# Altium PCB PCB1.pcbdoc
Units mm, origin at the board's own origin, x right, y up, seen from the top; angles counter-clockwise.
Board outline 82.72 x 77.76 mm, 2 copper layers (Top Layer, Bottom Layer); 33 components, 33 nets, 157 pads, 106 vias.
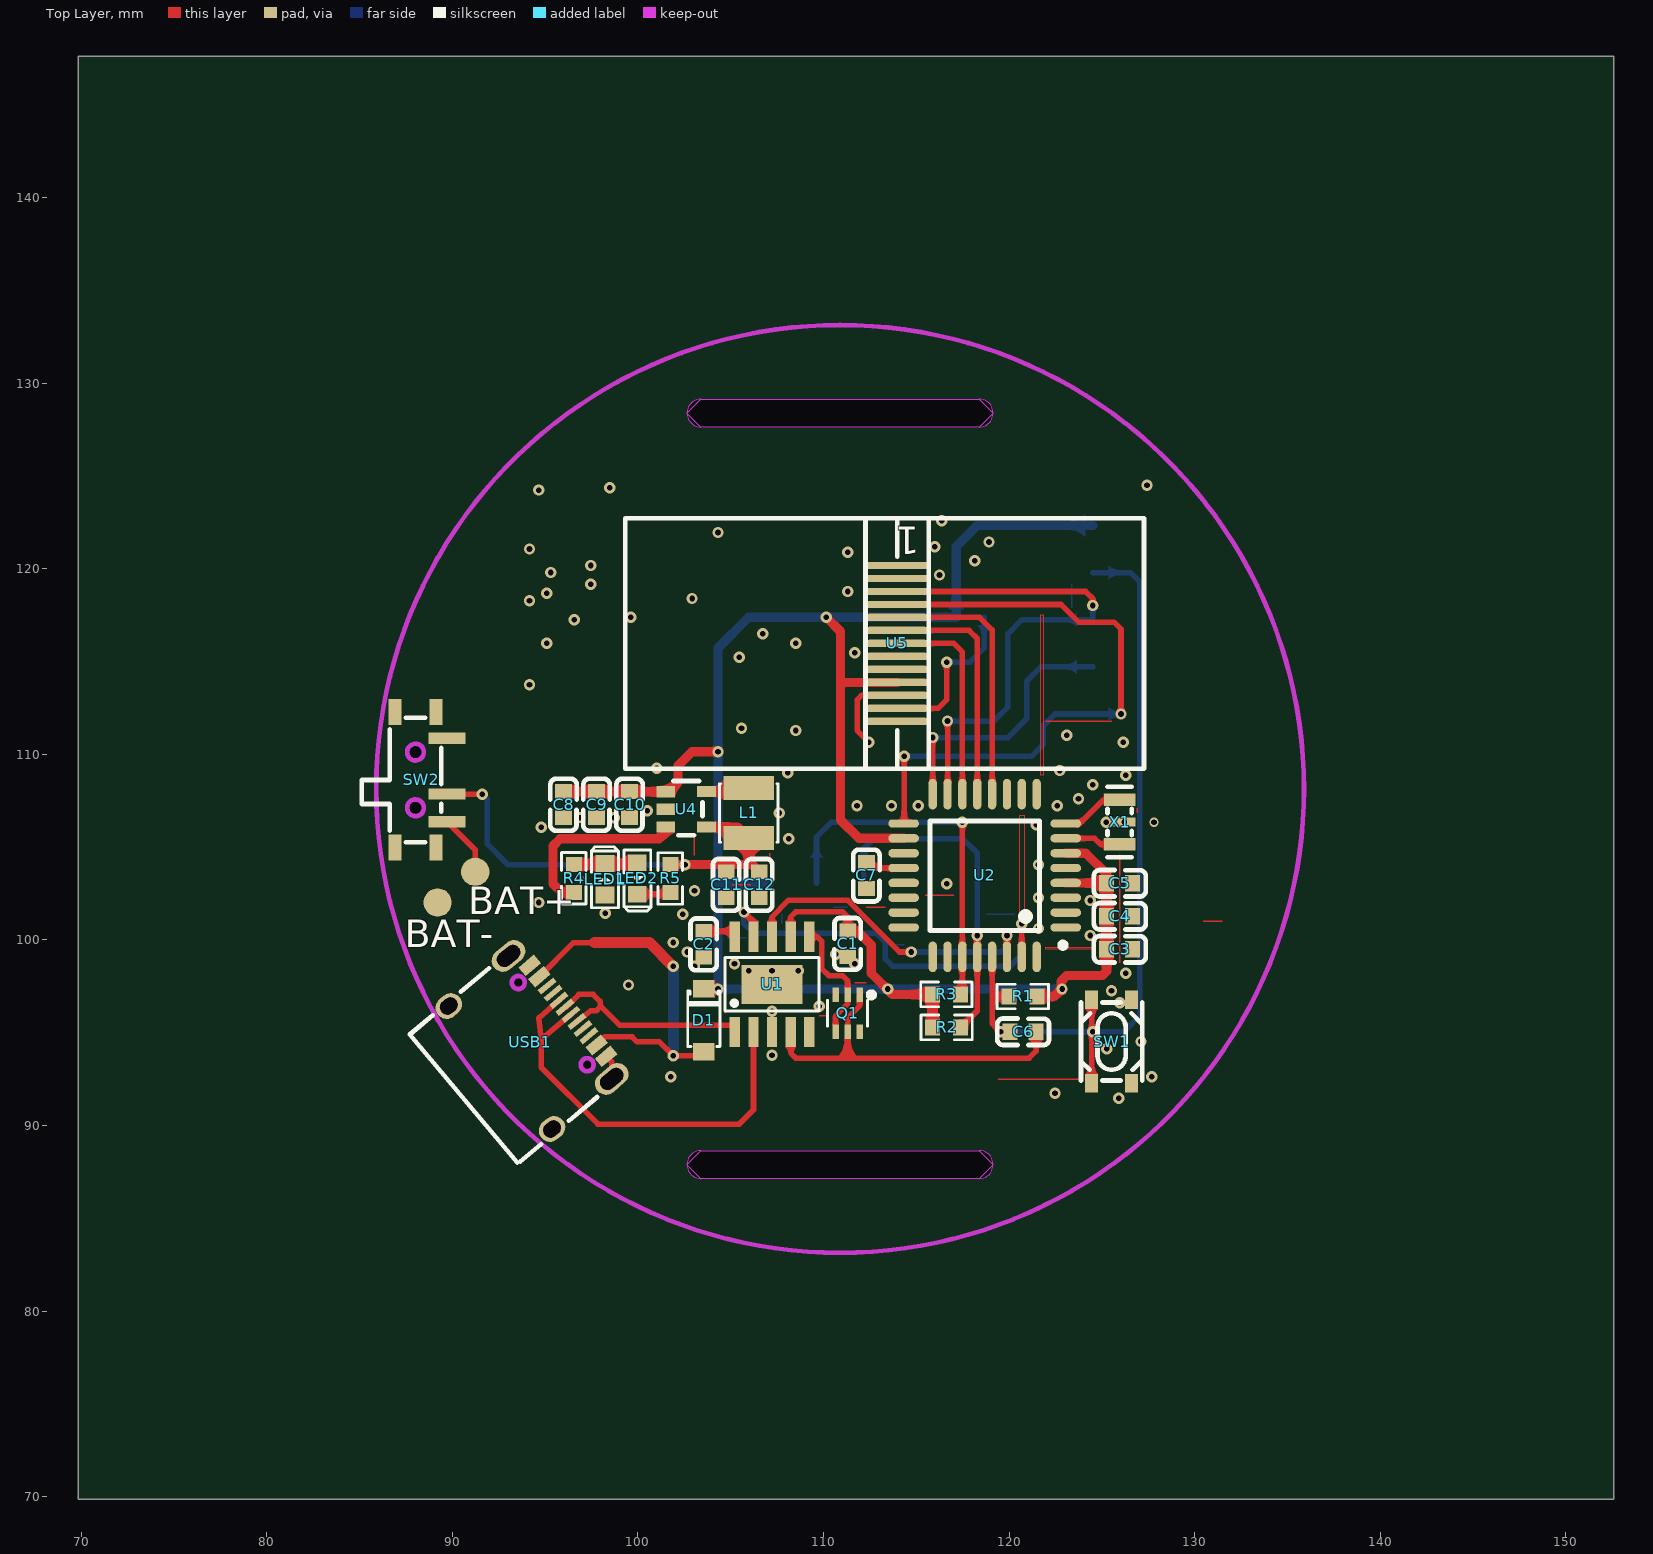
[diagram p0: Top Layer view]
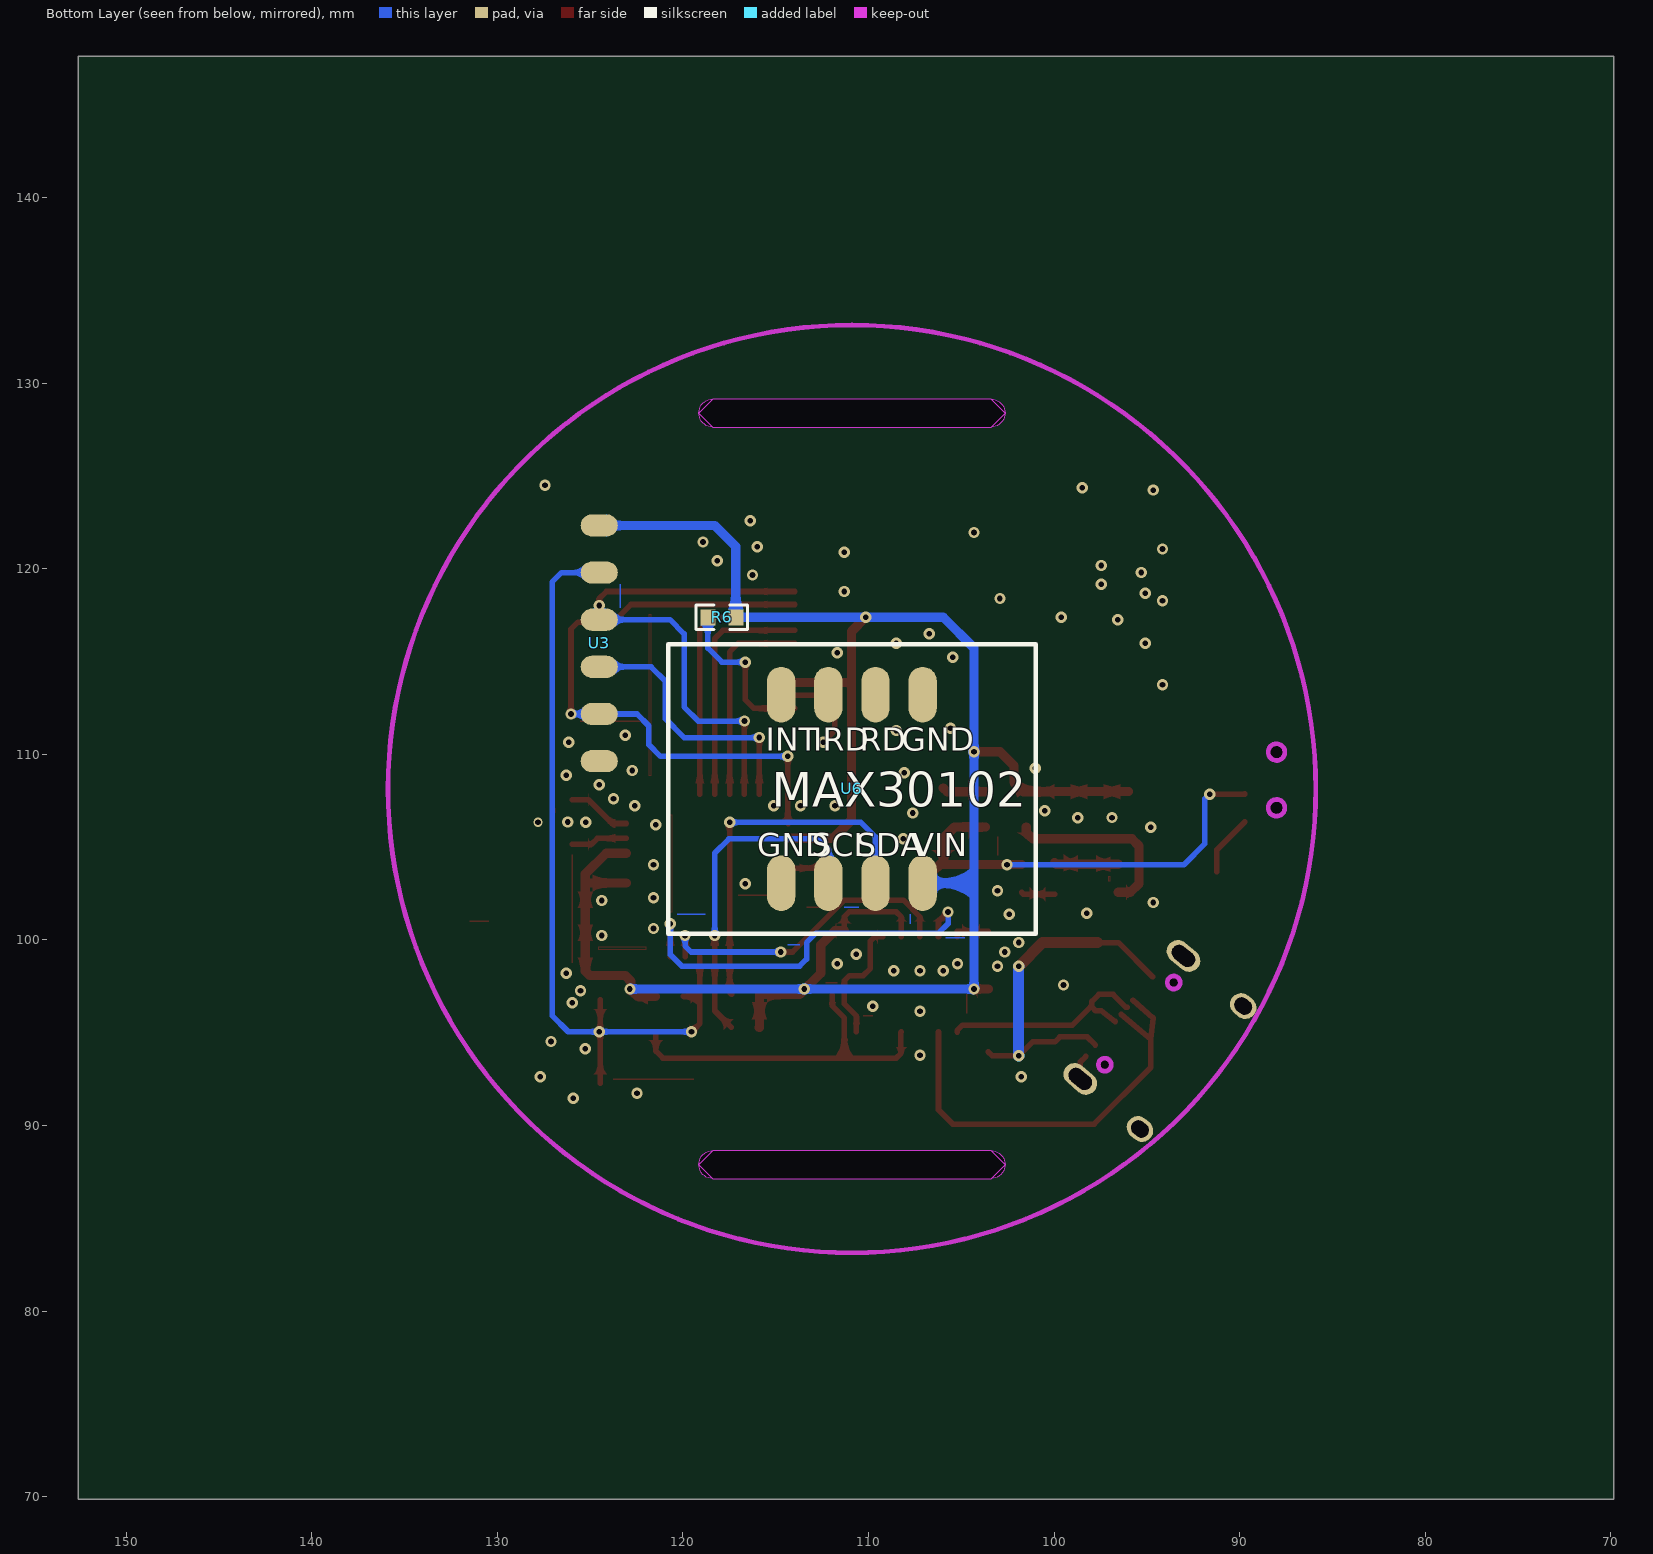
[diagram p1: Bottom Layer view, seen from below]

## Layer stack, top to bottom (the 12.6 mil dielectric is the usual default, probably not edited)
Top Layer: signal copper (thickness not stored)
Dielectric: dielectric 0.32, FR-4, Dk 4.8
Bottom Layer: signal copper (thickness not stored)

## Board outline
152.575,69.85 69.85,69.85 69.85,147.612 152.575,147.612
cut-out: 103.393,127.64 cw(c103.393,128.39) 102.643,128.39 cw(c103.393,128.39) 103.393,129.14 118.391,129.14 cw(c118.393,128.391) 118.393,129.141 cw(c118.393,128.391) 119.143,128.391 cw(c118.393,128.391) 118.393,127.64 cw(c118.392,128.39) 118.391,127.64 103.395,127.64
cut-out: 103.393,87.14 cw(c103.393,87.89) 102.643,87.89 cw(c103.393,87.89) 103.393,88.641 118.391,88.641 cw(c118.392,87.891) 118.393,88.641 cw(c118.393,87.89) 119.143,87.89 cw(c118.393,87.89) 118.393,87.14 cw(c118.393,87.89) 118.391,87.141 103.395,87.141

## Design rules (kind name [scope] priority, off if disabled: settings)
BoardOutlineClearance copperThickness1oz [All] p0: genericclearance=0.254 ignorepadtopadclearanceinfootprint=FALSE except(0: Arc-SplitContinuation Track-SplitContinuation SMDPad-SplitContinuation THPad-SplitContinuation Via-SplitContinuation Fill-SplitContinuation Poly-SplitContinuation Region-SplitContinuation Text-SplitContinuation; 0.152: Track-CutoutEdge SMDPad-CutoutEdge THPad-CutoutEdge Via-CutoutEdge Region-CutoutEdge; 0.3: Track-OutlineEdge SMDPad-OutlineEdge THPad-OutlineEdge Via-OutlineEdge Fill-OutlineEdge Region-OutlineEdge Poly-OutlineEdge Text-OutlineEdge Fill-CutoutEdge)
BoardOutlineClearance copperThickness2oz [All] p0: genericclearance=0.254 ignorepadtopadclearanceinfootprint=FALSE except(0: Arc-SplitContinuation Track-SplitContinuation SMDPad-SplitContinuation THPad-SplitContinuation Via-SplitContinuation Fill-SplitContinuation Poly-SplitContinuation Region-SplitContinuation Text-SplitContinuation; 0.152: Track-CutoutEdge SMDPad-CutoutEdge THPad-CutoutEdge Via-CutoutEdge Region-CutoutEdge; 0.3: Track-OutlineEdge SMDPad-OutlineEdge THPad-OutlineEdge Via-OutlineEdge Fill-OutlineEdge Region-OutlineEdge Poly-OutlineEdge Text-OutlineEdge Fill-CutoutEdge)
Clearance copperThickness1oz [(InNet('$1N2225') OR InNet('+5V') OR InNet('$1N2226') OR InNet('$1N2223') OR InNet('$1N4575') OR InNet('$1N2222') OR InNet('$1N2220') OR InNet('TXD') OR InNet('RXD') OR InNet('DTR') OR InNet('RTS') OR InNet('AREF') OR InNet('D13/SCK') OR InNet('D11/MOSI') OR InNet('D8') OR InNet('D9') OR InNet('D10') OR InNet('$1N1482') OR InNet('D12/MISO') OR InNet('A4/SDA') OR InNet('A5/SCL') OR InNet('RESET') OR InNet('$1N1204') OR InNet('$1N1203') OR InNet('BATIN') OR InNet('USBD-') OR InNet('+VBUS') OR InNet('USBD+') OR InNet('GND') OR InNet('EN') OR InNet('IO0') OR InNet('D4') OR InNet('D3'))] p1: gap=0.178 ignorepadtopadclearanceinfootprint=FALSE except(0.102: Track-Track; 0.152: Track-SMDPad SMDPad-SMDPad Track-THPad SMDPad-THPad THPad-THPad Track-Via SMDPad-Via THPad-Via Via-Via SMDPad-Fill THPad-Fill Via-Fill Fill-Fill Track-Region SMDPad-Region THPad-Region Via-Region Region-Region Track-Poly SMDPad-Poly THPad-Poly Via-Poly Fill-Poly Region-Poly Poly-Poly Track-Text SMDPad-Text THPad-Text Via-Text Fill-Text Region-Text Poly-Text Text-Text; 0.175: Track-Hole SMDPad-Hole THPad-Hole Via-Hole Fill-Hole Region-Hole Poly-Hole Text-Hole Sheet-Hole; 0.3: Track-Fill Fill-Region Track-Sheet SMDPad-Sheet THPad-Sheet Via-Sheet Fill-Sheet Region-Sheet Poly-Sheet Text-Sheet)
Clearance copperThickness2oz [All] p1: gap=0.178 ignorepadtopadclearanceinfootprint=FALSE except(0.152: Track-SMDPad SMDPad-SMDPad Track-THPad SMDPad-THPad THPad-THPad Track-Via SMDPad-Via THPad-Via Via-Via SMDPad-Fill THPad-Fill Via-Fill Fill-Fill Track-Region SMDPad-Region THPad-Region Via-Region Region-Region Track-Poly SMDPad-Poly THPad-Poly Via-Poly Fill-Poly Region-Poly Poly-Poly Track-Text SMDPad-Text THPad-Text Via-Text Fill-Text Region-Text Poly-Text Text-Text; 0.175: Track-Hole SMDPad-Hole THPad-Hole Via-Hole Fill-Hole Region-Hole Poly-Hole Text-Hole Sheet-Hole; 0.203: Track-Track; 0.3: Track-Fill Fill-Region Track-Sheet SMDPad-Sheet THPad-Sheet Via-Sheet Fill-Sheet Region-Sheet Poly-Sheet Text-Sheet)
DiffPairsRouting differentialPair [All] p1: maxuncoupledlength=10 minlimit=6 maxlimit=6 mostfreqgap=6 toplayer_minwidth=5 toplayer_prefwidth=10 toplayer_maxwidth=100 bottomlayer_minwidth=5 bottomlayer_prefwidth=10 bottomlayer_maxwidth=100
PasteMaskExpansion pasteMaskExpansion [All] p1: expansion=0
PlaneConnect innerPlane [All] p1: planeconnectstyle=Relief reliefexpansion=0.508 reliefentries=4 reliefconductorwidth=0.254 reliefairgap=0.254
PolygonConnect copperRegion [All] p1: connectstyle=Relief reliefentries=4 reliefconductorwidth=10 polygonreliefangle="90 Angle" airgapwidth=10
RoutingVias viaSize [All] p1: viastyle="Through Hole" holewidth=12.0078 minholewidth=11.811 maxholewidth=248.0314 width=24.0158 minwidth=19.685 maxwidth=393.7008
SolderMaskExpansion solderMaskExpansion [All] p1: useseparateexpansions=TRUE expansion=2 expansionbottom=2
Width copperThickness1oz [All] p1: maxlimit=100 minlimit=5 preferedwidth=10
Width copperThickness2oz [All] p1: maxlimit=100 minlimit=8 preferedwidth=10

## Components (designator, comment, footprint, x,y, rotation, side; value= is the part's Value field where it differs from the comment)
C1 "0.1u" C0603 111.3,99.798 r90 top
C2 "0.1u" C0603 103.544,99.769 r90 top
C3 "0.1u" C0603 125.959,99.499 r180 top
C4 "0.1u" C0603 125.959,101.277 r180 top
C5 "0.1u" C0603 125.959,103.055 r180 top
C6 "0.1u" C0603 120.752,95.054 r180 top
C7 "0.1u" C0603 112.316,103.478 r90 top
C8 "CL10A106MA8NRNC" C0603 95.991,107.295 r90 top
C9 "CL10A106MA8NRNC" C0603 97.769,107.295 r90 top
C10 "CC0603KRX7R9BB104" C0603 99.547,107.295 r90 top
C11 "CL10A106MA8NRNC" C0603 104.754,102.977 r90 top
C12 "CC0603KRX7R9BB104" C0603 106.532,102.977 r90 top
D1 "DSS24" SOD-123_L2.8-W1.8-LS3.7-RD 103.553,95.669 r270 top
L1 "FNR3015S2R2MT" IND-SMD_L3.0-W3.0_FNR30XXS 105.966,106.845 r90 top
LED1 "SZYY0603R" LED0603_BLUE 98.225,103.275 r90 top
LED2 "SZYY0603B" LED0603_BLUE 99.972,103.314 r270 top
Q1 "L2N7002SDW1T1G" SOT-363_L2.0-W1.3-P0.65-LS2.1-BL 111.3,96.05 r180 top
R1 "10K" R0603 120.742,96.956 r0 top
R2 "Res_0603" R0603 116.634,95.288 r0 top
R3 "Res_0603" R0603 116.625,97.066 r0 top
R4 "0603WAJ0472T5E" R0603 96.543,103.322 r270 top
R5 "0603WAJ0472T5E" R0603 101.75,103.314 r90 top
R6 "10K" R0603 117.904,117.386 r180 bottom
SW1 "TS3425BA" SW-SMD_4P-L4.2-W3.2-P2.15-LS4.6-1 125.524,94.526 r270 top
SW2 "拨动开关/MSK01-AG1.5/7.8*1.5*4.2mm" SW-TH_MSK01-AG1.5 88.313,108.623 r270 top
U1 "CH340K_C18208922" ESOP-10_L4.9-W3.9-P1.00-LS6.0-BL-EP 107.227,97.61 r0 top
U2 "ATMEGA328P-AU" TQFP-32_L7.0-W7.0-P0.80-LS9.0-BL 118.685,103.475 r90 top
U3 "BootloaderPad" BOOTLOADER 124.508,115.989 r180 bottom
U4 "ETA6093" SOT-23-5_L2.9-W1.6-P0.95-LS2.8-BR 102.595,107.041 r180 top
U5 "0.96寸tft屏(80x160px)" 0.96寸TFT屏幕焊接式 113.967,120.18 r180 top
U6 "MAX30102" MAX30102 112.175,106.794 r180 bottom
USB1 "TYPE-C 16PIN 2MD(073)" USB-C-SMD_TYPE-C-6PIN-2MD-073 94.409,94.653 r310 top
X1 "16MHz" OSC-SMD_3P-L3.2-W1.3-P1.2-L 125.959,106.357 r270 top

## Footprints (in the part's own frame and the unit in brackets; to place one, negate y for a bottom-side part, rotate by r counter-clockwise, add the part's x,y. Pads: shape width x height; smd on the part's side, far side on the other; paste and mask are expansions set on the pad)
0.96寸TFT屏幕焊接式 [mm]
  oval 3.4x0.4 smd: 1(0,0) 2(0,0.7) 3(0,1.4) 4(0,2.1) 5(0,2.8) 6(0,3.5) 7(0,4.2) 8(0,4.9) 9(0,5.6) 10(0,6.3) 11(0,7) 12(0,7.7) 13(0,8.4)
  silkscreen extent -13.3,-2.55 14.65,10.95
BOOTLOADER [mm]
  oval 2x1.2 smd: 1(0,-6.35) 2(0,-3.81) 3(0,-1.27) 4(0,1.27) 5(0,3.81) 6(0,6.35)
C0603 [mm]
  rect 0.8x0.9 smd: 1(-0.7,0) 2(0.7,0)
  silkscreen extent -1.41,-0.71 1.39,0.72
ESOP-10_L4.9-W3.9-P1.00-LS6.0-BL-EP [mm]
  rect 0.56x1.64 smd: 1(-2,-2.57) 2(-1,-2.57) 3(0,-2.57) 4(1,-2.57) 5(2,-2.57) 6(2,2.57) 7(1,2.57) 8(0,2.57) 9(-1,2.57) 10(-2,2.57)
  rect 3.3x2.1 smd: 11(0,0)
  silkscreen extent -2.53,-1.45 2.53,1.45
IND-SMD_L3.0-W3.0_FNR30XXS [mm]
  rect 1.3x2.72 smd: 1(1.35,0) 2(-1.35,0)
  silkscreen extent -1.58,-1.58 1.58,1.58
LED0603_BLUE [mm]
  rect 0.9x1 smd: 1(-0.85,0) 2(0.85,0)
  silkscreen extent -1.54,-0.73 1.75,0.73
MAX30102 [mm]
  oval 1.524x3 smd: 1(5.092,6.426) 2(2.552,6.426) 3(0.012,6.426) 4(-2.528,6.426) 5(-2.528,-3.734) 6(0.012,-3.734) 7(2.552,-3.734) 8(5.092,-3.734)
  silkscreen extent -8.62,-6.45 11.18,9.15
OSC-SMD_3P-L3.2-W1.3-P1.2-L [mm]
  rect 0.65x1.7 smd: 1(-1.2,0) 3(1.2,0)
  rect 0.5x1.7 smd: 2(0,0)
  silkscreen extent -1.9,-0.65 1.9,0.65
R0603 [mm]
  rect 0.806x0.864 smd: 1(-0.753,0) 2(0.753,0)
  silkscreen extent -1.39,-0.66 1.39,0.66
SOD-123_L2.8-W1.8-LS3.7-RD [mm]
  rect 0.95x1.15 smd: 1(-1.692,0) 2(1.692,0)
  silkscreen extent -1.58,-0.87 1.41,0.87
SOT-23-5_L2.9-W1.6-P0.95-LS2.8-BR [mm]
  rect 1x0.6 smd: 1(1.1,-0.95) 2(1.1,0) 3(1.1,0.95) 4(-1.1,0.95) 5(-1.1,-0.95)
  silkscreen extent -0.89,-1.52 0.7,1.4
SOT-363_L2.0-W1.3-P0.65-LS2.1-BL [mm]
  rect 0.35x0.78 smd: 1(-0.65,-0.99) 2(0,-0.99) 3(0.65,-0.99) 4(0.65,0.99) 5(0,0.99) 6(-0.65,0.99)
  silkscreen extent -1.43,-1.14 1.08,0.7
SW-SMD_4P-L4.2-W3.2-P2.15-LS4.6-1 [mm]
  rect 1x0.7 smd: 1(-2.25,1.075) 2(2.25,1.075) 3(-2.25,-1.075) 4(2.25,-1.075)
  silkscreen extent -2.1,-1.65 2.1,1.65
SW-TH_MSK01-AG1.5 [mm]
  rect 0.6x2 smd: 1(-2.25,1.4) 2(0.75,1.4) 3(2.25,1.4)
  rect 1.4x0.7 smd: 4(-3.65,-1.4) 4(-3.65,0.8) 4(3.65,-1.4) 4(3.65,0.8)
  Board Outline Layer circle w0.005: c1.5,-0.3 r0.45
  Board Outline Layer circle w0.005: c-1.5,-0.3 r0.45
  Board Outline Layer circle w0.254: c1.5,-0.3 r0.45
  Board Outline Layer circle w0.254: c-1.5,-0.3 r0.45
  Multi-Layer board cut-out: 1.5,0.15 1.305,0.105 1.148,-0.02 1.061,-0.2 1.061,-0.4 1.148,-0.581 1.305,-0.706 1.5,-0.75 1.5,-0.75 1.725,-0.69 1.89,-0.525 1.95,-0.3 1.89,-0.075 1.725,0.09 1.5,0.15
  Multi-Layer board cut-out: -1.5,0.15 -1.695,0.105 -1.852,-0.02 -1.939,-0.2 -1.938,-0.4 -1.852,-0.581 -1.695,-0.706 -1.5,-0.75 -1.5,-0.75 -1.275,-0.69 -1.11,-0.525 -1.05,-0.3 -1.11,-0.075 -1.275,0.09 -1.5,0.15
  silkscreen extent -3.35,-3.2 3.35,1.09
TQFP-32_L7.0-W7.0-P0.80-LS9.0-BL [mm]
  oval 0.45x1.65 smd: 1(-2.8,-4.369) 2(-2,-4.369) 3(-1.2,-4.369) 4(-0.4,-4.369) 5(0.4,-4.369) 6(1.2,-4.369) 7(2,-4.369) 8(2.8,-4.369) 17(2.8,4.369) 18(2,4.369) 19(1.2,4.369) 20(0.4,4.369) 21(-0.4,4.369) 22(-1.2,4.369) 23(-2,4.369) 24(-2.8,4.369)
  oval 1.65x0.45 smd: 9(4.382,-2.8) 10(4.382,-2) 11(4.382,-1.2) 12(4.382,-0.4) 13(4.382,0.4) 14(4.382,1.2) 15(4.382,2) 16(4.382,2.8) 25(-4.381,2.8) 26(-4.381,2) 27(-4.381,1.2) 28(-4.381,0.4) 29(-4.381,-0.4) 30(-4.381,-1.2) 31(-4.381,-2) 32(-4.381,-2.8)
  silkscreen extent -3.91,-4.36 2.94,2.95
USB-C-SMD_TYPE-C-6PIN-2MD-073 [mm]
  rect 0.6x1.1 smd: 1(-3.2,2.375) 2(-2.4,2.375) 11(2.4,2.375) 12(3.2,2.375)
  rect 0.3x1.1 smd: 3(-1.75,2.375) 4(-1.25,2.375) 5(-0.75,2.375) 6(-0.25,2.375) 7(0.25,2.375) 8(0.75,2.375) 9(1.25,2.375) 10(1.75,2.375)
  oval 1.2x2 hole 0.8 slot 1.4 at 90 deg: 13(-4.325,1.825)
  oval 1.2x1.5 hole 0.8 slot 1 at 90 deg: 13(-4.325,-2.375)
  oval 1.2x2 hole 0.8 slot 1.4 at 90 deg copper offset 0,0: 14(4.325,1.825)
  oval 1.2x1.5 hole 0.8 slot 1 at 90 deg copper offset 0,0: 14(4.325,-2.375)
  Board Outline Layer circle w0.005: c-2.89,1.305 r0.35
  Board Outline Layer circle w0.005: c2.89,1.305 r0.35
  Board Outline Layer circle w0.254: c-2.89,1.305 r0.35
  Board Outline Layer circle w0.254: c2.89,1.305 r0.35
  Multi-Layer board cut-out: -2.665,1.573 -2.804,1.644 -2.959,1.648 -3.101,1.584 -3.201,1.465 -3.24,1.314 -3.209,1.161 -3.115,1.037 -3.115,1.037 -2.951,0.96 -2.77,0.976 -2.622,1.08 -2.545,1.244 -2.561,1.425 -2.665,1.573
  Multi-Layer board cut-out: 3.115,1.573 2.976,1.644 2.821,1.648 2.679,1.584 2.578,1.465 2.54,1.314 2.571,1.161 2.665,1.037 2.665,1.037 2.804,0.966 2.959,0.962 3.101,1.026 3.201,1.145 3.24,1.296 3.209,1.449 3.115,1.573
  silkscreen extent -4.5,-4.97 4.57,0.6

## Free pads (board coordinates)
  round 1.524 smd: 1(91.234,103.67) 2(89.202,102.019)

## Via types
v1: diameter 0.61, hole 0.305, Top Layer to Bottom Layer, 105 vias
v2: diameter 0.5, hole 0.305, Top Layer to Bottom Layer, 1 vias

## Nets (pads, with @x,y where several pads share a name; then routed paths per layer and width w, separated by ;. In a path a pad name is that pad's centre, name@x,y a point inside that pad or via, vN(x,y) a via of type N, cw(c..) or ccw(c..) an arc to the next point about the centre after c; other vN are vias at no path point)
$1N1203: U2.7 X1.3 | length 3
  Top Layer w0.3: U2.7 124.608,105.475 124.926,105.157 X1.3
$1N1204: U2.8 X1.1 | length 3.4
  Top Layer w0.3: U2.8 123.811,106.275 125.093,107.557 X1.1
$1N1482: R6.1 U5.12 | length 8.9
  Top Layer w0.3: U5.12 116.173,112.479 116.634,112.941 v1(116.634,114.973)
  Bottom Layer w0.3: v1(116.634,114.973) 117.904,114.973 118.657,115.726 R6.1
$1N2220: L1.1 U4.5 | length 2.4
  Top Layer w0.5: U4.5 105.762,107.991 L1.1
$1N2222: C11.2 C12.2 L1.2 R5.2 SW2.2 U4.4 | length 24.8
  Top Layer w0.3: SW2.2 89.725,107.861 v1(91.615,107.861)
  Top Layer w0.5: R5.2 C12.2@106.141,104.067 ; U4.4 105.37,106.091 L1.2 105.966,104.243 C12.2@106.141,104.067 ; C12.2 C12.2@106.141,104.067
  Bottom Layer w0.3: v1(91.615,107.861) 91.869,107.607 91.869,105.194 93.012,104.051 v1(102.537,104.051)
$1N2223: LED2.2 R5.1 | length 1.8
  Top Layer w0.3: LED2.2 101.653,102.464 R5.1
$1N2225: R4.2 U4.3 | length 10
  Top Layer w0.5: R4.2 95.89,102.569 95.425,103.035 95.425,105.067 95.806,105.448 101.14,105.448 101.495,105.802 U4.3
$1N2226: LED1.2 LED2.1 R4.1 | length 3.5
  Top Layer w0.5: R4.1 99.884,104.076 LED2.1
$1N4575: C2.2 U1.10 | length 2
  Top Layer w0.3: C2.2 105.227,100.469 U1.10
+5V: C1.2 C3.2 C4.2 C5.2 C8.2 C9.2 C10.2 D1.1 R1.2 R2.1 R3.1 R6.2 U1.7 U2.4 U2.6 U2.18 U3.6 U4.1 U5.10 U6.8 | length 122
  Top Layer w0.3: U1.7 108.227,101.231 108.506,101.511 111.046,101.511 111.3,101.257 C1.2
  Top Layer w0.5: C8.2 C9.2 C10.2 100.422,107.995 100.426,107.991 U4.1 101.651,107.991 102.156,108.496 102.156,109.385 102.918,110.147 v1(104.315,110.147) ; D1.1 v1(104.315,97.361) ; v1(110.151,117.386) 110.919,116.618 110.919,113.703 ; C1.2 111.805,100.498 112.57,99.733 112.57,98.209 113.713,97.066 R3.1 115.872,95.296 R2.1 ; U5.10 111.096,113.879 110.919,113.703 ; U2.18 111.908,105.475 110.919,106.464 110.919,113.703 ; R1.2 122.44,96.956 122.793,97.31 122.793,97.764 123.111,98.082 125.016,98.082 125.259,98.325 C3.2 C4.2 C5.2 ; U2.4 125.239,103.075 C5.2 ; U2.6 124.138,104.675 125.259,103.553 C5.2
  Bottom Layer w0.5: U6.8 104.345,103.06 104.315,103.091 ; v1(122.857,97.361) v1(113.459,97.361) v1(104.315,97.361) 104.315,103.091 ; U3.6 118.285,122.339 117.15,121.204 R6.2 v1(110.151,117.386) 105.966,117.386 104.315,115.735 v1(104.315,110.147) 104.315,103.091
+VBUS: D1.2 USB1.2 USB1.11 | length 19.8
  Top Layer w0.3: USB1.2 96.527,99.86 97.66,99.86 ; USB1.11 98.21,94.78 99.682,94.78 99.951,94.511 101.155,94.511 v1(101.902,93.764) 103.34,93.764 D1.2
  Top Layer w0.6: 97.66,99.86 100.619,99.86 v1(101.902,98.577)
  Bottom Layer w0.6: v1(101.902,93.764) 101.915,93.777 101.915,98.563 v1(101.902,98.577)
A4/SDA: R3.2 U2.27 U6.7 | length 20
  Top Layer w0.3: R3.2 117.485,97.172 U2.27 v1(117.485,106.337)
  Bottom Layer w0.3: U6.7 109.623,105.549 110.411,106.337 v1(117.485,106.337)
A5/SCL: R2.2 U2.28 U6.6 | length 18.3
  Top Layer w0.3: R2.2 118.285,96.186 U2.28 ; U2.28 v1(118.285,100.241)
  Bottom Layer w0.3: U6.6 112.163,104.914 112.697,105.448 117.523,105.448 118.285,104.686 v1(118.285,100.241)
AREF: C7.2 U2.20 | length 2.1
  Top Layer w0.3: C7.2 112.619,103.875 U2.20
BATIN: pad.1 SW2.3 | length 3.3
  Top Layer w0.3: SW2.3 91.234,104.851 pad.1
D3: U2.1
D4: U2.2
D8: U2.12 U5.5 | length 14.3
  Top Layer w0.3: U5.5 118.418,117.379 119.085,116.712 U2.12
D9: U2.13 U5.6 | length 12.9
  Top Layer w0.3: U5.6 117.848,116.679 118.285,116.243 U2.13
D10: U2.14 U5.7 | length 11.4
  Top Layer w0.3: U5.7 117.024,115.979 117.485,115.518 U2.14
D11/MOSI: U2.15 U3.4 U5.3 | length 28.2
  Top Layer w0.3: U5.3 124.13,118.779 124.508,118.402 v1(124.508,118.021) ; U2.15 v1(116.685,111.798)
  Bottom Layer w0.3: v1(116.685,111.798) 119.174,111.798 119.936,112.56 119.936,116.497 120.698,117.259 U3.4 v1(124.508,118.021)
D12/MISO: U2.16 U3.3 | length 14.4
  Top Layer w0.3: U2.16 v1(115.885,110.909)
  Bottom Layer w0.3: v1(115.885,110.909) 119.936,110.909 120.952,111.925 120.952,113.957 121.714,114.719 U3.3
D13/SCK: U2.17 U3.2 U5.4 | length 34
  Top Layer w0.3: U5.4 122.798,118.079 123.746,117.132 125.651,117.132 126.032,116.751 v1(126.032,112.179) ; U2.17 114.348,106.306 v1(114.348,109.893)
  Bottom Layer w0.3: v1(114.348,109.893) 121.206,109.893 121.841,110.528 121.841,111.544 122.476,112.179 U3.2 v1(126.032,112.179)
DTR: C6.1 Q1.1 Q1.5 U1.4 | length 19.3
  Top Layer w0.3: U1.4 108.252,95.014 108.252,93.891 108.506,93.637 111.293,93.637 ; Q1.1 111.95,96.445 111.3,95.796 Q1.5 111.3,93.643 111.293,93.637 ; C6.1 121.46,95.046 121.46,94.018 121.079,93.637 111.293,93.637
EN: Q1.3
GND: C1.1 C2.1 C3.1 C4.1 C5.1 C7.1 C8.1 C9.1 C10.1 C11.1 C12.1 LED1.1 pad.2 SW1.1 SW1.2 U1.3 U1.11 U2.3 U2.5 U2.21 U3.1 U4.2 U5.8 U5.11 U5.13 U6.1 U6.5 USB1.1 USB1.12 USB1.13 USB1.14 X1.2 | length 6.1
  Top Layer w0.3: USB1.12 98.587,93.426 USB1.14@98.587,92.513 ; v1(112.443,110.655) 111.808,111.29 111.808,112.941 112.047,113.179 U5.11
  other v1: 125.905,91.478 122.476,91.732 101.775,92.621 127.683,92.621 107.227,93.786 125.27,94.145 127.113,94.526 107.227,96.156 109.776,96.431 125.967,96.615 125.524,97.264 99.489,97.574 126.286,98.209 105.966,98.336 108.633,98.336 107.227,98.338 103.045,98.59 105.204,98.717 111.681,98.717 110.665,99.225 102.664,99.352 101.902,99.86 124.381,100.241 121.587,100.622 102.41,101.384 98.244,101.434 94.663,102.019 124.381,102.128 121.587,102.273 103.045,102.654 116.634,103.035 121.587,104.054 108.125,105.448 94.79,106.083 121.46,106.21 125.236,106.337 126.205,106.357 98.727,106.591 96.874,106.595 107.617,106.845 100.505,106.972 111.808,107.226 113.664,107.226 115.11,107.226 122.603,107.226 123.746,107.607 124.508,108.369 126.286,108.877 108.076,109.004 122.73,109.131 101.013,109.258 126.159,110.655 123.111,111.036 108.506,111.29 105.585,111.417 94.155,113.751 105.458,115.227 111.681,115.481 95.088,115.988 108.506,115.989 106.728,116.497 96.568,117.259 99.616,117.386 94.155,118.275 102.918,118.402 95.088,118.686 111.3,118.783 97.457,119.164 116.253,119.672 95.298,119.799 97.457,120.18 118.158,120.434 111.3,120.891 94.155,121.069 115.999,121.196 118.92,121.45 104.315,121.958 116.38,122.593 94.663,124.244 98.473,124.371 127.429,124.498
  other v2: 127.81,106.337
IO0: Q1.6
RESET: C6.2 R1.1 SW1.3 SW1.4 U2.29 U3.5 | length 44.2
  Top Layer w0.3: U2.29 119.085,97.032 ; R1.1 119.162,96.956 119.085,97.032 ; C6.2 v1(119.534,95.054) 119.085,95.503 119.085,97.032 ; SW1.4 SW1.3
  Bottom Layer w0.3: v1(119.534,95.054) v1(124.508,95.054) 126.179,95.054 127.048,95.923 127.048,119.291 126.54,119.799 U3.5
RTS: Q1.2 Q1.4 U1.6 | length 6.9
  Top Layer w0.3: U1.6 109.651,100.18 109.898,99.933 109.898,98.468 110.284,98.082 111.024,98.082 111.3,97.806 Q1.2 111.3,96.558 110.65,95.908 Q1.4
RXD: U1.8 U2.30 | length 17.1
  Top Layer w0.3: U1.8 107.227,101.247 108.125,102.146 111.3,102.146 114.094,99.352 v1(114.729,99.352) ; v1@119.809,100.241 119.885,100.164 U2.30
  Bottom Layer w0.3: v1(114.729,99.352) 119.555,99.352 119.885,99.681 v1(119.885,100.241)
TXD: U1.9 U2.31 | length 22.3
  Top Layer w0.3: v1(105.712,101.511) 106.227,100.996 U1.9 ; U2.31 v1(120.685,100.876)
  Bottom Layer w0.3: v1(105.712,101.511) 105.712,100.876 106.22,100.368 112.824,100.368 113.332,99.86 113.332,98.971 113.713,98.59 120.063,98.59 120.685,99.212 v1(120.685,100.876)
USBD+: U1.1 USB1.6 USB1.8 | length 12
  Top Layer w0.3: USB1.6 96.127,96.371 96.822,97.066 97.584,97.066 97.965,96.685 97.965,96.389 ; USB1.8 97.457,96.177 97.753,96.177 97.965,96.389 ; U1.1 105.227,95.114 104.927,95.415 99.014,95.415 98.04,96.389 97.965,96.389
USBD-: U1.2 USB1.5 USB1.7 | length 23.4
  Top Layer w0.3: USB1.5 94.663,95.796 94.79,94.653 ; USB1.7 94.79,94.653 ; U1.2 106.227,90.849 105.458,90.081 97.838,90.081 94.79,93.129 94.79,94.653
pads on no net: SW2.1 SW2.4 U1.5 U2.9 U2.10 U2.11 U2.19 U2.22 U2.23 U2.24 U2.25 U2.26 U2.32 U5.1 U5.2 U5.9 U6.2 U6.3 U6.4 USB1.3 USB1.4 USB1.9 USB1.10
copper on no net: | length 90.4
  Top Layer w0.01: 96.982,103.195 97.078,103.195 97.078,103.416 96.982,103.416 96.982,103.195 ; 103.045,104.559 103.047,104.559 103.047,105.575 103.045,105.575 103.045,104.559 ; 104.696,96.05 104.698,96.05 104.698,97.066 104.696,97.066 104.696,96.05 ; 105.075,102.966 105.075,102.969 106.091,102.969 106.091,102.966 105.075,102.966 ; 107.109,104.305 107.111,104.305 107.111,104.686 107.109,104.686 107.109,104.305 ; 109.776,95.92 109.776,95.923 110.284,95.923 110.284,95.92 109.776,95.92 ; 111.681,97.701 111.681,97.703 112.316,97.703 112.316,97.701 111.681,97.701 ; 111.805,104.813 111.808,104.813 111.808,104.94 111.805,104.94 111.805,104.813 ; 112.316,101.762 112.316,101.765 113.332,101.765 113.332,101.762 112.316,101.762 ; 115.491,102.4 115.491,102.402 117.015,102.402 117.015,102.4 115.491,102.4 ; 119.428,92.494 119.428,92.496 123.746,92.496 123.746,92.494 119.428,92.494 ; 120.571,101.511 120.825,101.511 120.825,106.718 120.571,106.718 120.571,101.511 ; 121.714,108.877 121.841,108.877 121.841,117.513 121.714,117.513 121.714,108.877 ; 121.968,99.496 121.968,99.606 124.562,99.606 124.562,99.496 121.968,99.496 ; 121.968,111.795 125.524,111.795 125.524,111.798 121.968,111.798 121.968,111.795 ; 125.964,98.763 125.967,98.763 125.967,104.586 125.964,104.586 125.964,98.763 ; 126.918,106.845 126.921,106.845 126.921,107.099 126.918,107.099 126.918,106.845 ; 130.477,101 130.477,101.003 131.493,101.003 131.493,101 130.477,101
  Bottom Layer w0.01: 104.823,100.114 104.823,100.116 105.839,100.116 105.839,100.114 104.823,100.114 ; 107.741,100.876 107.744,100.876 107.744,101.384 107.741,101.384 107.741,100.876 ; 110.538,101.765 111.3,101.765 111.3,101.767 110.538,101.767 110.538,101.765 ; 113.713,99.733 113.713,99.735 114.348,99.735 114.348,99.733 113.713,99.733 ; 118.793,101.381 118.793,101.384 120.317,101.384 120.317,101.381 118.793,101.381 ; 123.365,117.894 123.367,117.894 123.367,119.164 123.365,119.164 123.365,117.894

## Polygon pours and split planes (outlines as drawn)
GND on Bottom Layer (solid, remove dead copper, pour order 2): 76.2,140.081 140.97,140.081 140.97,76.2 76.2,76.2
GND on Top Layer (solid, remove dead copper, pour order 0): 81.455,141.262 146.225,141.262 146.225,77.381 81.455,77.381

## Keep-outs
Board Outline Layer:
  circle w0.254: c110.893,108.14 r25
  region: 103.393,127.64 102.643,128.39 103.393,129.14 118.391,129.14 118.393,129.141 119.143,128.391 118.393,127.64 118.391,127.64 103.395,127.64
  region: 103.393,87.14 102.643,87.89 103.393,88.641 118.391,88.641 118.393,88.641 119.143,87.89 118.393,87.14 118.391,87.141 103.395,87.141
  lines w0.025: 102.643,87.89 ccw(c103.393,87.89) 103.393,87.14 103.395,87.141 118.391,87.141 ccw(c118.393,87.89) 118.393,87.14 ccw(c118.393,87.89) 119.143,87.89 ccw(c118.393,87.89) 118.393,88.641 ccw(c118.392,87.891) 118.391,88.641 103.393,88.641 ccw(c103.393,87.89) 102.643,87.89 ; 102.643,128.39 ccw(c103.393,128.39) 103.393,127.64 103.395,127.64 118.391,127.64 ccw(c118.392,128.39) 118.393,127.64 ccw(c118.393,128.391) 119.143,128.391 ccw(c118.393,128.391) 118.393,129.141 ccw(c118.393,128.391) 118.391,129.14 103.393,129.14 ccw(c103.393,128.39) 102.643,128.39

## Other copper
Top Layer:
  region net $1N2225: 95.89,102.319 95.89,102.819 ccw(c95.89,103.054) 96.111,102.972 96.111,102.166 ccw(c95.89,102.084)
  region net +5V: 97.191,108.245 97.191,107.745 ccw(c97.191,105.795) 96.441,107.595 96.441,108.395 ccw(c97.191,110.195)
  region net +5V: 96.569,107.745 96.569,108.245 ccw(c96.569,110.195) 97.319,108.395 97.319,107.595 ccw(c96.569,105.795)
  region net $1N2226: 97.725,104.326 97.725,103.826 ccw(c97.725,101.914) 96.975,103.672 96.975,104.479 ccw(c97.725,106.238)
  region net $1N2226: 96.975,103.826 96.975,104.326 ccw(c96.975,105.58) 97.725,104.575 97.725,103.675 ccw(c96.975,101.887)
  region net +5V: 98.969,108.245 98.969,107.745 ccw(c98.969,105.795) 98.219,107.595 98.219,108.395 ccw(c98.969,110.195)
  region net +5V: 98.347,107.745 98.347,108.245 ccw(c98.347,110.195) 99.097,108.395 99.097,107.595 ccw(c98.347,105.795)
  region net $1N2226: 98.722,103.826 98.722,104.326 ccw(c98.722,105.446) 99.472,104.614 99.472,103.714 ccw(c98.722,101.256)
  region net $1N2226: 99.475,104.326 99.475,103.826 ccw(c99.475,101.887) 98.725,103.675 98.725,104.575 ccw(c99.475,105.58)
  region net +5V: 100.422,108.245 100.422,107.745 ccw(c100.422,107.067) 99.997,107.595 99.997,108.395 ccw(c100.422,108.923)
  region net $1N2223: 100.922,102.614 100.922,102.314 ccw(c100.922,101.751) 100.472,102.089 100.472,102.839 ccw(c100.922,103.176)
  region net +5V: 100.426,107.741 100.426,108.241 ccw(c100.426,111.498) 100.995,108.291 100.995,107.691 ccw(c100.426,104.483)
  region net $1N2223: 100.868,102.314 100.868,102.614 ccw(c100.868,103.176) 101.318,102.839 101.318,102.157 ccw(c100.868,101.589)
  region net $1N2225: 101.385,105.339 100.963,105.624 ccw(c100.857,105.731) 100.995,105.791 101.995,105.791 ccw(c103.207,103.518)
  region net +5V: 101.862,108.556 102.333,108.319 ccw(c103.209,107.442) 101.995,107.691 101.067,108.291 ccw(c101.067,109.616)
  region net +5V: 103.949,109.897 103.949,110.397 104.016,110.399 104.08,110.405 104.191,110.424 104.273,110.443 104.315,110.452 104.315,109.841 104.273,109.85 104.191,109.869 104.08,109.888 104.016,109.894
  region net +5V: 103.949,97.111 103.949,97.611 104.016,97.613 104.08,97.619 104.191,97.638 104.273,97.657 104.315,97.666 104.315,97.056 104.273,97.064 104.191,97.083 104.08,97.102 104.016,97.109
  region net $1N4575: 104.444,100.619 104.444,100.319 ccw(c104.444,99.756) 103.994,100.094 103.994,100.844 ccw(c104.444,101.181)
  region net +5V: 104.315,97.611 104.315,97.111 ccw(c104.357,96.886) 104.128,96.886 104.128,97.836 ccw(c104.357,97.836)
  region net $1N2222: 103.856,105.841 103.856,106.341 ccw(c104.606,107.676) 104.606,106.144 104.606,105.466 ccw(c103.856,104.903)
  region net $1N2220: 103.856,107.741 103.856,108.241 ccw(c103.856,109.178) 104.606,108.616 104.606,107.545 ccw(c103.856,106.21)
  region net $1N2222: 104.945,106.341 104.945,105.841 ccw(c104.945,100.191) 104.195,105.791 104.195,106.391 ccw(c104.945,111.991)
  region net $1N2220: 104.945,108.241 104.945,107.741 ccw(c104.945,102.091) 104.195,107.691 104.195,108.291 ccw(c104.945,113.891)
  region net $1N4575: 104.497,100.319 104.497,100.619 ccw(c104.497,101.181) 104.947,100.844 104.947,100.094 ccw(c104.497,99.756)
  region net TXD: 106.113,101.322 105.9,101.11 105.858,101.143 105.805,101.173 105.747,101.196 105.695,101.206 106.016,101.527 106.027,101.475 106.049,101.418 106.079,101.364
  region net $1N2222: 106.216,104.243 105.716,104.243 ccw(c105.045,104.243) 105.341,104.844 106.591,104.844 ccw(c106.886,104.243)
  region net TXD: 105.66,101.35 106.153,101.282 ccw(c107.581,102.71) 106.507,101 105.947,101 ccw(c104.061,99.75)
  region net RXD: 107.077,101.247 107.377,101.247 ccw(c107.678,101.247) 107.507,101 106.947,101 ccw(c106.776,101.247)
  region net DTR: 108.402,93.891 108.102,93.891 ccw(c107.675,93.891) 107.947,94.22 108.507,94.22 ccw(c108.971,93.891)
  region net +5V: 108.077,101.231 108.377,101.231 ccw(c108.648,101.231) 108.507,101 107.947,101 ccw(c107.805,101.231)
  region net RTS: 109.651,100.33 109.651,100.03 ccw(c109.754,99.805) 109.507,99.805 109.507,100.555 ccw(c109.754,100.555)
  region net RTS: 110.5,95.899 110.8,95.899 ccw(c114.861,95.899) 110.825,95.449 110.475,95.449 ccw(c106.438,95.899)
  region net DTR: 111.15,94.686 cw(c109.65,94.686) 110.85,93.787 111.293,93.637 111.75,93.787 cw(c112.95,94.686) 111.45,94.686
  region net DTR: 111.45,94.219 111.15,94.219 ccw(c107.088,94.219) 111.125,94.669 111.475,94.669 ccw(c115.511,94.219)
  region net RTS: 111.15,97.806 111.45,97.806 ccw(c114.293,97.806) 111.475,97.43 111.125,97.43 ccw(c108.306,97.806)
  region net +5V: 111.15,101.257 111.45,101.257 ccw(c111.849,101.257) 111.675,100.898 110.925,100.898 ccw(c110.751,101.257)
  region net +5V: 111.805,100.748 111.805,100.248 ccw(c111.982,100.098) 111.75,100.098 111.75,100.898 ccw(c111.982,100.898)
  region net DTR: 112.1,96.445 111.8,96.445 ccw(c110.954,96.445) 111.775,96.65 112.125,96.65 ccw(c112.945,96.445)
  region net AREF: 113.216,104.025 113.216,103.725 ccw(c112.766,101.83) 112.766,103.778 112.766,104.25 ccw(c113.216,104.587)
  region net AREF: 113.266,103.725 113.266,104.025 113.349,104.028 113.428,104.037 113.566,104.062 113.667,104.088 113.716,104.1 113.716,103.65 113.667,103.662 113.566,103.687 113.428,103.713 113.349,103.722
  region net D13/SCK: 114.498,109.476 114.198,109.476 114.192,109.529 114.175,109.588 114.15,109.645 114.12,109.689 114.575,109.689 114.545,109.645 114.521,109.588 114.504,109.529
  region net D13/SCK: 114.198,106.95 114.498,106.95 114.501,106.785 114.51,106.709 114.526,106.64 114.538,106.61 114.553,106.583 114.571,106.559 114.593,106.538 114.618,106.522 114.649,106.51 114.683,106.502 114.723,106.5 113.973,106.5 114.012,106.502 114.047,106.51 114.077,106.522 114.103,106.538 114.125,106.559 114.143,106.583 114.158,106.61 114.17,106.64 114.186,106.709 114.194,106.785
  region net RXD: 114.312,99.202 114.312,99.502 114.365,99.508 114.425,99.524 114.481,99.549 114.525,99.579 114.525,99.124 114.481,99.154 114.425,99.179 114.365,99.195
  region net +5V: 114.719,96.816 114.719,97.316 ccw(c114.719,98.952) 115.469,97.498 115.469,96.633 ccw(c114.719,95.179)
  region net D11/MOSI: 115.917,118.929 115.917,118.629 115.834,118.627 115.755,118.622 115.617,118.604 115.467,118.579 115.467,118.979 115.617,118.954 115.755,118.937 115.834,118.932
  region net D13/SCK: 115.917,118.229 115.917,117.929 115.834,117.927 115.755,117.922 115.617,117.904 115.467,117.879 115.467,118.279 115.617,118.254 115.755,118.237 115.834,118.232
  region net D8: 115.917,117.529 115.917,117.229 115.834,117.227 115.755,117.222 115.617,117.204 115.467,117.179 115.467,117.579 115.617,117.554 115.755,117.537 115.834,117.532
  region net D9: 115.917,116.829 115.917,116.529 115.834,116.527 115.755,116.522 115.617,116.504 115.467,116.479 115.467,116.879 115.617,116.854 115.755,116.837 115.834,116.832
  region net D10: 115.917,116.129 115.917,115.829 115.834,115.827 115.755,115.822 115.617,115.804 115.467,115.779 115.467,116.179 115.617,116.154 115.755,116.137 115.834,116.132
  region net $1N1482: 115.917,112.629 115.917,112.329 115.834,112.327 115.755,112.322 115.617,112.304 115.467,112.279 115.467,112.679 115.617,112.654 115.755,112.637 115.834,112.632
  region net +5V: 116.122,95.883 115.622,95.883 ccw(c113.71,95.883) 115.469,96.633 116.275,96.633 ccw(c118.034,95.883)
  region net +5V: 115.622,96.47 116.122,96.47 ccw(c117.94,96.47) 116.284,95.72 115.477,95.72 ccw(c113.605,96.47)
  region net D12/MISO: 115.735,108.906 116.035,108.906 116.038,108.823 116.047,108.745 116.073,108.606 116.098,108.506 116.11,108.456 115.66,108.456 115.672,108.506 115.698,108.606 115.723,108.745 115.732,108.823
  region net D12/MISO: 116.035,110.492 115.735,110.492 115.729,110.545 115.712,110.604 115.688,110.661 115.658,110.705 116.113,110.705 116.083,110.661 116.058,110.604 116.041,110.545
  region net $1N1482: 116.784,114.556 116.484,114.556 116.478,114.609 116.461,114.668 116.436,114.725 116.406,114.769 116.861,114.769 116.831,114.725 116.807,114.668 116.79,114.609
  region net D11/MOSI: 116.535,108.906 116.835,108.906 116.838,108.823 116.847,108.745 116.873,108.606 116.898,108.506 116.91,108.456 116.46,108.456 116.472,108.506 116.498,108.606 116.523,108.745 116.532,108.823
  region net D11/MOSI: 116.835,111.381 116.535,111.381 116.529,111.434 116.512,111.493 116.488,111.55 116.458,111.594 116.913,111.594 116.883,111.55 116.858,111.493 116.841,111.434
  region net A4/SDA: 117.335,97.948 117.635,97.948 ccw(c118.399,97.948) 117.782,97.498 117.11,97.498 ccw(c116.773,97.948)
  region net A4/SDA: 117.335,100.143 117.635,100.143 117.638,100.06 117.647,99.982 117.673,99.843 117.698,99.743 117.71,99.693 117.26,99.693 117.272,99.743 117.298,99.843 117.323,99.982 117.332,100.06
  region net A4/SDA: 117.635,98.043 117.335,98.043 117.332,98.126 117.323,98.205 117.298,98.343 117.272,98.444 117.26,98.493 117.71,98.493 117.698,98.444 117.673,98.343 117.647,98.205 117.638,98.126
  region net D10: 117.335,108.906 117.635,108.906 117.638,108.823 117.647,108.745 117.673,108.606 117.698,108.506 117.71,108.456 117.26,108.456 117.272,108.506 117.298,108.606 117.323,108.745 117.332,108.823
  region net A4/SDA: 117.635,105.92 117.335,105.92 117.329,105.973 117.312,106.032 117.288,106.089 117.258,106.133 117.713,106.133 117.683,106.089 117.658,106.032 117.641,105.973
  region net A5/SCL: 117.766,95.879 117.949,95.638 ccw(c118.586,95.16) 117.79,95.16 117.289,95.72 ccw(c117.289,96.515)
  region net A5/SCL: 118.435,99.824 118.135,99.824 118.129,99.877 118.112,99.936 118.087,99.993 118.057,100.037 118.512,100.037 118.482,99.993 118.458,99.936 118.441,99.877
  region net A5/SCL: 118.135,100.143 118.435,100.144 118.438,100.068 118.447,100.009 118.459,99.961 118.472,99.919 118.486,99.876 118.498,99.828 118.507,99.769 118.51,99.694 118.06,99.693 118.063,99.768 118.072,99.827 118.084,99.875 118.097,99.918 118.111,99.96 118.123,100.008 118.132,100.067
  region net D9: 118.135,108.906 118.435,108.907 118.438,108.831 118.447,108.772 118.459,108.724 118.472,108.682 118.486,108.639 118.498,108.591 118.507,108.532 118.51,108.457 118.06,108.456 118.063,108.531 118.072,108.59 118.084,108.638 118.097,108.681 118.111,108.723 118.123,108.771 118.132,108.83
  region net A5/SCL: 118.435,98.043 118.135,98.043 118.132,98.126 118.123,98.205 118.098,98.343 118.072,98.444 118.06,98.493 118.51,98.493 118.498,98.444 118.473,98.343 118.447,98.205 118.438,98.126
  region net D8: 118.935,108.906 119.235,108.906 119.238,108.823 119.247,108.745 119.273,108.606 119.298,108.506 119.31,108.456 118.86,108.456 118.872,108.506 118.898,108.606 118.923,108.745 118.932,108.823
  region net RESET: 119.235,98.043 118.935,98.043 118.932,98.126 118.923,98.205 118.898,98.343 118.872,98.444 118.86,98.493 119.31,98.493 119.298,98.444 119.273,98.343 119.247,98.205 119.238,98.126
  region net RESET: 119.134,95.243 119.346,95.455 119.388,95.421 119.442,95.391 119.499,95.369 119.551,95.358 119.23,95.037 119.22,95.09 119.197,95.147 119.167,95.2
  region net RESET: 119.162,96.806 119.162,97.106 ccw(c119.162,97.618) 119.586,97.331 119.586,96.581 ccw(c119.162,96.294)
  region net RESET: 119.989,96.806 ccw(c119.989,95.709) 119.235,96.506 119.085,97.032 119.235,97.406 ccw(c119.989,98.203) 119.989,97.106
  region net RESET: 119.534,94.904 119.534,95.204 ccw(c119.378,95.429) 119.652,95.429 119.652,94.679 ccw(c119.378,94.679)
  region net RESET: 119.951,95.204 119.951,94.904 119.898,94.898 119.838,94.881 119.782,94.857 119.738,94.827 119.738,95.281 119.782,95.251 119.838,95.227 119.898,95.21
  region net RXD: 120.035,99.824 119.735,99.823 119.729,99.877 119.712,99.936 119.688,99.993 119.658,100.037 120.112,100.037 120.082,99.993 120.058,99.937 120.041,99.877
  region net RXD: 119.735,100.143 120.035,100.143 120.038,100.06 120.047,99.982 120.073,99.843 120.098,99.743 120.11,99.693 119.66,99.693 119.672,99.743 119.698,99.843 119.723,99.982 119.732,100.06
  region net TXD: 120.835,100.459 120.535,100.459 120.529,100.512 120.512,100.571 120.488,100.628 120.458,100.672 120.912,100.672 120.883,100.628 120.858,100.571 120.841,100.512
  region net TXD: 120.535,100.143 120.835,100.143 120.838,100.06 120.847,99.982 120.873,99.843 120.898,99.743 120.91,99.693 120.46,99.693 120.472,99.743 120.498,99.843 120.523,99.982 120.532,100.06
  region net DTR: 121.61,94.154 121.31,94.154 ccw(c120.747,94.154) 121.085,94.604 121.835,94.604 ccw(c122.172,94.154)
  region net +5V: 122.44,97.206 122.44,96.706 ccw(c122.44,95.811) 121.899,96.524 121.899,97.388 ccw(c122.44,98.101)
  region net +5V: 122.711,96.874 122.358,97.228 122.41,97.283 122.448,97.329 122.501,97.407 122.555,97.483 122.594,97.529 122.647,97.583 123.066,97.139 123.011,97.091 122.965,97.056 122.887,97.008 122.81,96.96 122.765,96.924
  region net $1N1204: 124.057,106.733 124.044,106.296 123.956,106.206 123.913,106.164 123.868,106.127 123.821,106.095 123.771,106.071 123.716,106.055 123.654,106.05 123.654,106.5 123.714,106.505 123.77,106.52 123.823,106.543 123.874,106.573 123.922,106.608 123.968,106.647
  region net $1N1203: 124.104,105.625 124.104,105.325 124.021,105.322 123.942,105.313 123.804,105.287 123.703,105.262 123.654,105.25 123.654,105.7 123.703,105.688 123.804,105.662 123.942,105.637 124.021,105.628
  region net RESET: 124.599,95.826 124.299,95.826 ccw(c123.692,95.826) 124.099,96.276 124.799,96.276 ccw(c125.205,95.826)
  region net RESET: 124.299,93.225 124.599,93.225 ccw(c125.205,93.225) 124.799,92.775 124.099,92.775 ccw(c123.692,93.225)
  region net RESET: 124.599,94.597 124.299,94.685 124.295,94.737 124.284,94.795 124.267,94.851 124.245,94.898 124.691,94.81 124.671,94.792 124.653,94.769 124.624,94.714 124.605,94.654
  region net RESET: 124.299,95.423 124.599,95.511 124.605,95.453 124.624,95.393 124.653,95.339 124.671,95.316 124.691,95.297 124.245,95.209 124.267,95.256 124.284,95.313 124.295,95.371
  region net +5V: 124.109,102.825 124.109,103.325 ccw(c124.109,104.976) 124.859,103.505 124.859,102.605 ccw(c124.109,101.436)
  region net D11/MOSI: 124.358,118.402 124.658,118.402 124.664,118.355 124.682,118.307 124.707,118.262 124.735,118.224 124.28,118.224 124.309,118.262 124.334,118.307 124.351,118.355
  region net $1N1203: 124.926,105.007 124.926,105.307 ccw(c124.926,105.49) 125.109,105.482 125.109,104.832 ccw(c124.926,104.823)
  region net $1N1204: 125.093,107.407 125.093,107.707 ccw(c124.131,107.882) 125.109,107.882 125.109,107.232 ccw(c124.131,107.232)
  region net +5V: 125.509,101.855 125.009,101.855 ccw(c123.059,101.855) 124.859,102.605 125.659,102.605 ccw(c127.459,101.855)
  region net +5V: 125.509,100.077 125.009,100.077 ccw(c123.059,100.077) 124.859,100.827 125.659,100.827 ccw(c127.459,100.077)
  region net +5V: 125.009,102.477 125.509,102.477 ccw(c127.459,102.477) 125.659,101.727 124.859,101.727 ccw(c123.059,102.477)
  region net +5V: 125.009,100.699 125.509,100.699 ccw(c127.459,100.699) 125.659,99.949 124.859,99.949 ccw(c123.059,100.699)
  region net +5V: 125.509,98.325 125.009,98.325 ccw(c123.186,98.325) 124.859,99.049 125.659,99.049 ccw(c127.332,98.325)
  region net D13/SCK: 125.882,112.595 126.182,112.595 126.188,112.542 126.205,112.483 126.229,112.426 126.259,112.382 125.804,112.382 125.834,112.426 125.859,112.483 125.876,112.542
Bottom Layer:
  region net +5V: 104.065,97.727 104.565,97.727 104.567,97.66 104.573,97.596 104.592,97.485 104.611,97.403 104.62,97.361 104.01,97.361 104.018,97.403 104.037,97.485 104.056,97.596 104.062,97.66
  region net +5V: 104.565,109.78 104.065,109.78 104.062,109.848 104.056,109.911 104.037,110.023 104.018,110.104 104.01,110.147 104.62,110.147 104.611,110.104 104.592,110.023 104.573,109.911 104.567,109.848
  region net +5V: 104.065,110.513 104.565,110.513 104.567,110.445 104.573,110.382 104.592,110.27 104.611,110.189 104.62,110.147 104.01,110.147 104.018,110.189 104.037,110.27 104.056,110.382 104.062,110.445
  region net +5V: 104.681,97.611 104.681,97.111 104.614,97.109 104.55,97.102 104.439,97.083 104.357,97.064 104.315,97.056 104.315,97.666 104.357,97.657 104.439,97.638 104.55,97.619 104.614,97.613
  region net +5V: 106.065,102.811 ccw(c106.065,100.311) 104.565,102.311 104.315,103.091 104.565,103.81 ccw(c106.065,105.81) 106.065,103.31
  region net +5V: 105.571,102.811 105.571,103.31 105.711,103.311 105.846,103.316 105.973,103.33 106.032,103.342 106.087,103.357 106.137,103.377 106.183,103.402 106.223,103.432 106.257,103.469 106.284,103.512 106.304,103.562 106.317,103.619 106.321,103.686 106.321,102.436 106.317,102.502 106.304,102.559 106.284,102.609 106.257,102.652 106.223,102.689 106.183,102.719 106.137,102.744 106.087,102.764 106.032,102.779 105.973,102.791 105.846,102.805 105.711,102.81
  region net A4/SDA: 109.473,104.912 109.773,104.912 109.777,104.849 109.788,104.785 109.807,104.719 109.833,104.656 109.865,104.597 109.903,104.543 109.948,104.497 109.998,104.462 109.248,104.462 109.298,104.497 109.342,104.543 109.381,104.597 109.413,104.656 109.439,104.719 109.458,104.785 109.469,104.849
  region net A5/SCL: 112.013,104.912 112.313,104.912 112.317,104.849 112.328,104.785 112.347,104.719 112.373,104.656 112.405,104.597 112.443,104.543 112.488,104.497 112.538,104.462 111.788,104.462 111.838,104.497 111.882,104.543 111.921,104.597 111.953,104.656 111.979,104.719 111.998,104.785 112.009,104.849
  region net +5V: 113.093,97.111 113.093,97.611 113.16,97.613 113.224,97.619 113.335,97.638 113.417,97.657 113.459,97.666 113.459,97.056 113.417,97.064 113.335,97.083 113.224,97.102 113.16,97.109
  region net +5V: 113.825,97.611 113.825,97.111 113.758,97.109 113.694,97.102 113.583,97.083 113.501,97.064 113.459,97.056 113.459,97.666 113.501,97.657 113.583,97.638 113.694,97.619 113.758,97.613
  region net D13/SCK: 114.765,110.043 114.765,109.743 114.711,109.736 114.652,109.72 114.596,109.695 114.551,109.665 114.551,110.12 114.596,110.09 114.652,110.065 114.711,110.049
  region net RXD: 115.146,99.502 115.146,99.202 115.092,99.195 115.033,99.179 114.977,99.154 114.932,99.124 114.932,99.579 114.977,99.549 115.033,99.524 115.092,99.508
  region net D12/MISO: 116.302,111.059 116.302,110.759 116.249,110.752 116.189,110.736 116.133,110.711 116.089,110.681 116.089,111.136 116.133,111.106 116.189,111.081 116.249,111.065
  region net $1N1482: 117.051,115.123 117.051,114.823 116.997,114.816 116.938,114.8 116.882,114.775 116.837,114.745 116.837,115.2 116.882,115.17 116.938,115.145 116.997,115.129
  region net D11/MOSI: 117.102,111.948 117.102,111.648 117.049,111.641 116.989,111.625 116.933,111.6 116.889,111.57 116.889,112.025 116.933,111.995 116.989,111.97 117.049,111.954
  region net +5V: 116.9,118.568 117.4,118.568 ccw(c119.312,118.568) 117.554,117.818 116.747,117.818 ccw(c114.988,118.568)
  region net A4/SDA: 117.068,106.187 117.068,106.487 117.122,106.493 117.181,106.509 117.237,106.534 117.282,106.564 117.282,106.109 117.237,106.139 117.181,106.164 117.122,106.18
  region net A5/SCL: 118.135,100.657 118.435,100.657 118.441,100.604 118.458,100.545 118.482,100.488 118.512,100.444 118.057,100.444 118.087,100.488 118.112,100.545 118.129,100.604
  region net $1N1482: 118.807,116.503 118.507,116.503 ccw(c117.944,116.503) 118.282,116.953 119.032,116.953 ccw(c119.369,116.503)
  region net RESET: 119.951,95.204 119.951,94.904 119.898,94.898 119.838,94.881 119.782,94.857 119.738,94.827 119.738,95.281 119.782,95.251 119.838,95.227 119.898,95.21
  region net RXD: 120.035,99.824 119.735,99.824 119.729,99.877 119.712,99.936 119.687,99.993 119.657,100.037 120.112,100.037 120.082,99.993 120.058,99.936 120.041,99.877
  region net TXD: 120.835,100.459 120.535,100.459 120.529,100.512 120.512,100.571 120.488,100.628 120.458,100.672 120.912,100.672 120.883,100.628 120.858,100.571 120.841,100.512
  region net +5V: 122.491,97.111 122.491,97.611 122.558,97.613 122.622,97.619 122.733,97.638 122.815,97.657 122.857,97.666 122.857,97.056 122.815,97.064 122.733,97.083 122.622,97.102 122.558,97.109
  region net D12/MISO: 123.189,114.569 123.189,114.869 123.246,114.874 123.308,114.888 123.371,114.91 123.435,114.939 123.495,114.973 123.551,115.011 123.6,115.052 123.639,115.094 123.639,114.344 123.6,114.385 123.551,114.426 123.495,114.464 123.435,114.498 123.371,114.527 123.308,114.549 123.246,114.563
  region net D11/MOSI: 123.189,117.109 123.189,117.409 123.246,117.414 123.308,117.428 123.371,117.45 123.435,117.479 123.495,117.513 123.551,117.551 123.6,117.592 123.639,117.634 123.639,116.884 123.6,116.925 123.551,116.966 123.495,117.004 123.435,117.038 123.371,117.067 123.308,117.089 123.246,117.103
  region net +5V: 123.358,122.089 123.358,122.589 123.428,122.592 123.497,122.604 123.564,122.621 123.63,122.643 123.693,122.67 123.753,122.699 123.864,122.764 123.958,122.828 124.033,122.884 124.084,122.923 124.108,122.938 124.108,121.739 124.084,121.754 124.033,121.793 123.958,121.849 123.864,121.914 123.753,121.978 123.693,122.007 123.63,122.034 123.564,122.056 123.497,122.073 123.428,122.085
  region net RESET: 124.091,94.904 124.091,95.204 124.144,95.21 124.204,95.227 124.26,95.251 124.304,95.281 124.304,94.827 124.26,94.857 124.204,94.881 124.144,94.898
  region net D11/MOSI: 124.658,117.604 124.358,117.604 124.352,117.657 124.335,117.716 124.31,117.773 124.28,117.817 124.735,117.817 124.705,117.773 124.681,117.716 124.664,117.657
  region net D11/MOSI: 124.358,118.021 124.658,118.021 124.663,117.981 124.677,117.948 124.699,117.92 124.728,117.897 124.762,117.88 124.8,117.868 124.841,117.861 124.883,117.858 124.133,117.858 124.175,117.861 124.215,117.868 124.253,117.88 124.287,117.897 124.316,117.92 124.338,117.948 124.353,117.981
  region net RESET: 124.925,95.204 124.925,94.904 124.871,94.898 124.812,94.881 124.756,94.857 124.711,94.827 124.711,95.281 124.756,95.251 124.812,95.227 124.871,95.21
  region net RESET: 125.826,119.949 125.826,119.649 125.769,119.643 125.708,119.629 125.644,119.607 125.581,119.578 125.52,119.544 125.464,119.506 125.415,119.465 125.376,119.424 125.376,120.174 125.415,120.132 125.464,120.091 125.52,120.053 125.581,120.019 125.644,119.99 125.708,119.968 125.769,119.954
  region net D13/SCK: 125.826,112.329 125.826,112.029 125.769,112.023 125.708,112.009 125.644,111.987 125.581,111.958 125.52,111.924 125.464,111.886 125.415,111.845 125.376,111.804 125.376,112.553 125.415,112.512 125.464,112.471 125.52,112.433 125.581,112.399 125.644,112.37 125.708,112.348 125.769,112.334
  region net D13/SCK: 125.615,112.029 125.615,112.329 125.668,112.335 125.728,112.351 125.784,112.376 125.828,112.406 125.828,111.951 125.784,111.981 125.728,112.006 125.668,112.022

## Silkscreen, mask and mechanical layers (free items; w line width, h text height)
Top Silkscreen Layer:
  text "BAT+" at 90.853,101.384 h1.5
  text "BAT-" at 87.424,99.606 h1.5
Mechanical Layer:
  lines w0.025: 102.643,87.89 ccw(c103.393,87.89) 103.393,87.14 103.395,87.141 118.391,87.141 ccw(c118.393,87.89) 118.393,87.14 ccw(c118.393,87.89) 119.143,87.89 ccw(c118.393,87.89) 118.393,88.641 ccw(c118.392,87.891) 118.391,88.641 103.393,88.641 ccw(c103.393,87.89) 102.643,87.89 ; 102.643,128.39 ccw(c103.393,128.39) 103.393,127.64 103.395,127.64 118.391,127.64 ccw(c118.392,128.39) 118.393,127.64 ccw(c118.393,128.391) 119.143,128.391 ccw(c118.393,128.391) 118.393,129.141 ccw(c118.393,128.391) 118.391,129.14 103.393,129.14 ccw(c103.393,128.39) 102.643,128.39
